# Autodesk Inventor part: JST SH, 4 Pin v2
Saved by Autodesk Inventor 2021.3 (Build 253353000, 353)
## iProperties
Created: 2023-09
Part Number: JST SH, 4 Pin v2
Material: Generic
Document SubType Name: Modeling
Designer: AdminForWorker
Density: 1 g/cm^3
Appearance: Default
Title: JST SH, 4 Pin v2
Author: AdminForWorker
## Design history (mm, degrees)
feature "Body1"
feature "Body2"
feature "Body3"
feature "Body4"
feature "Body5"
feature "Body6"
feature "Body7"
body "Solid1"
body "Solid2"
body "Solid3"
body "Solid4"
body "Solid5"
body "Solid6"
body "Solid7"
